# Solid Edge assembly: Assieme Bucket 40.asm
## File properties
Title: LAVABO BUCKET 40
Author: 0
Template: Iso Assembly.asm
Last saved by: PIM_1
Revision: 5
Application: Solid Edge
Tipo di contenuto documento: 1
Document Number: 8803
Revision: 0
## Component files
Lavabo Bucket 40.par
Perno filettato.par
Boccola portaasciugamani.par
Portasciugamano Bucket 40.par
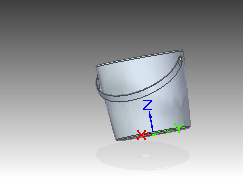
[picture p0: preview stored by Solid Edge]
